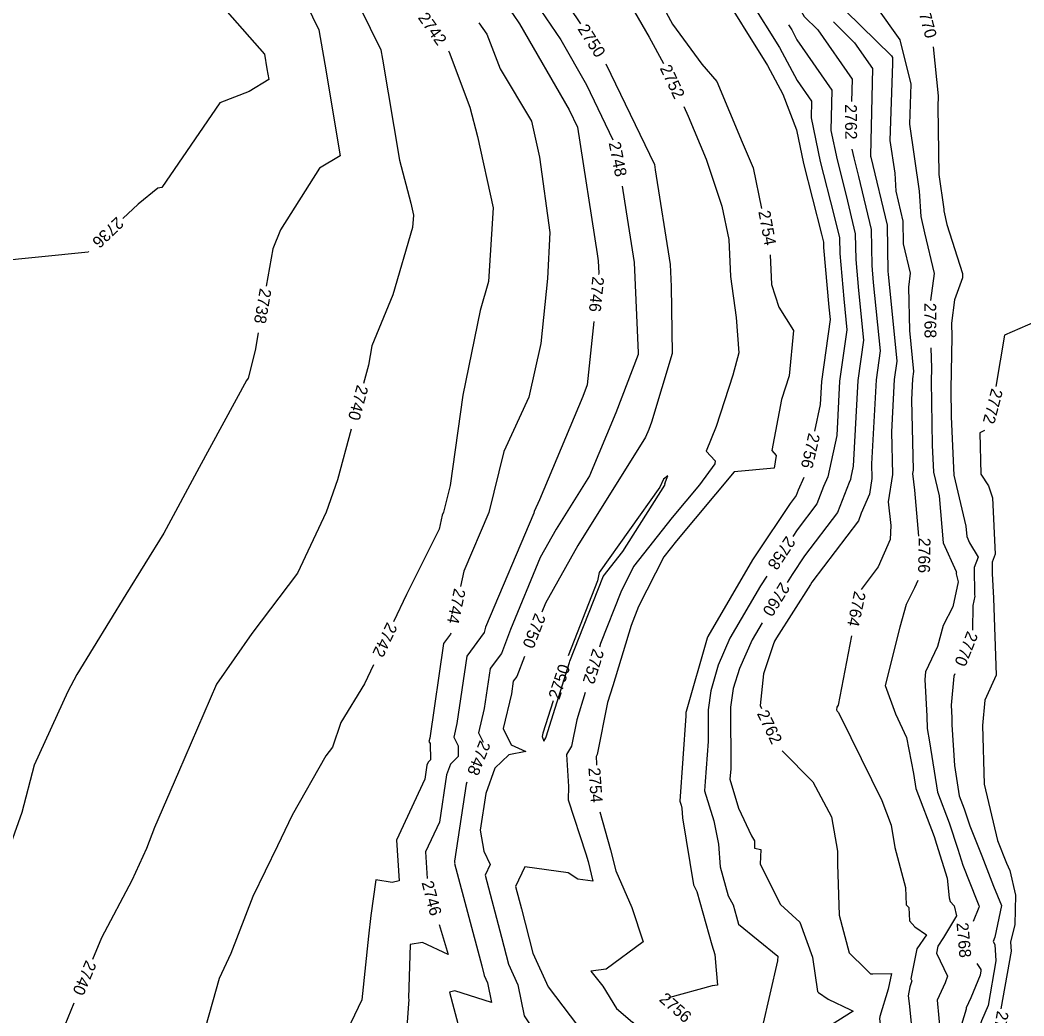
# Model space of a CAD drawing. Extents: x 1326424 to 1329294, y 1001359 to 1003823.
# Drawn here: x 1328101.5 to 1328270.7, y 1002132.9 to 1002300.7 of the extents above; entities that cross this region are included whole.
import ezdxf

# ---------------------------------------------------------------- set-up
doc = ezdxf.new("R2010")
doc.units = 0
doc.layers.add('Prop Rem of Exist Asph Pvmt', color=7, linetype='Continuous')
doc.layers.add('Scratch_Level_3', color=7, linetype='Continuous')

msp = doc.modelspace()

# ---------------------------------------------------------------- linework, layer by layer
at = {"layer": 'Prop Rem of Exist Asph Pvmt'}
for points in [[(1328137.93, 1002329.46), (1328145.65, 1002320.15), (1328150.16, 1002314.83), (1328157, 1002306.62), (1328162.33, 1002295.68), (1328162.6, 1002294.14), (1328165.48, 1002277.1), (1328167.37, 1002269.89), (1328167.81, 1002267.87), (1328167.68, 1002265.79), (1328164.34, 1002254.4), (1328160.8, 1002245.85), (1328160.23, 1002242.57), (1328159.4, 1002239.5)], [(1328231.01, 1002299.92), (1328231.55, 1002299.05), (1328232.44, 1002297.39), (1328238.31, 1002288.9), (1328238.16, 1002282.13), (1328239.19, 1002277.18), (1328240.74, 1002271.14), (1328242.27, 1002264.73), (1328242.34, 1002260.37), (1328242.8, 1002255.13), (1328243.64, 1002246.77), (1328242.69, 1002239.99), (1328241.92, 1002225.56), (1328241.53, 1002223.72), (1328241.44, 1002223.31), (1328241.21, 1002222.79), (1328239.29, 1002217.78), (1328233.73, 1002210.44), (1328231.64, 1002207.31), (1328230.79, 1002205.97)], [(1328157.31, 1002231.78), (1328155, 1002223.25), (1328153.09, 1002217.79), (1328148.26, 1002207.56), (1328140.6, 1002197.4), (1328134.65, 1002188.82), (1328128.24, 1002174.02), (1328124.2, 1002164.7), (1328122.82, 1002161.15), (1328120.34, 1002155.77), (1328115.25, 1002146.09), (1328113.72, 1002142.46)], [(1328226.58, 1002199.17), (1328224.91, 1002196.32), (1328222.77, 1002191.46), (1328221.68, 1002188.13), (1328221.25, 1002184.96), (1328221.27, 1002174.56), (1328221.13, 1002172.86), (1328222.57, 1002167.97), (1328224.77, 1002163.31), (1328225.27, 1002162.46), (1328225.27, 1002161.2), (1328226.33, 1002160.97), (1328226.23, 1002158.54), (1328229.69, 1002151.71), (1328232.93, 1002148.73), (1328235.05, 1002142.83), (1328235.9, 1002137.07), (1328236.05, 1002136.9), (1328237.72, 1002135.76), (1328241.47, 1002133.99), (1328241.88, 1002133.77), (1328236.13, 1002130.1)], [(1328110.61, 1002135.08), (1328109.05, 1002131.38), (1328107.66, 1002126.41), (1328107.1, 1002124.52), (1328107.44, 1002122.93), (1328106.9, 1002102.21), (1328106.04, 1002097.76), (1328108.22, 1002082.7), (1328108.65, 1002078.85), (1328112.24, 1002054.51), (1328112.26, 1002052.45), (1328109.23, 1002044.54), (1328107.76, 1002040.24), (1328107.08, 1002037.12)]]:
    msp.add_lwpolyline(points, dxfattribs=at)
at = {"layer": 'Scratch_Level_3'}
for points in [[(1328139.62, 1002379.77), (1328143.78, 1002373.87), (1328144.33, 1002372.95), (1328151.49, 1002363.95), (1328151.79, 1002363.59), (1328157.98, 1002355.78), (1328156.78, 1002354.76), (1328157.22, 1002349.14), (1328166.57, 1002337.91), (1328169.93, 1002333.87), (1328170.75, 1002332.84), (1328180.63, 1002321.17), (1328181.53, 1002319.97), (1328190.61, 1002308.04), (1328195.95, 1002300.06)], [(1328151, 1002373.46), (1328154.11, 1002369.54), (1328160.69, 1002361.71), (1328161.49, 1002360.69), (1328172.13, 1002345.68), (1328175.32, 1002341.89), (1328183.23, 1002335.42), (1328185.56, 1002332.78), (1328190.87, 1002323.83), (1328193.47, 1002319.61), (1328199.59, 1002311.45), (1328202.83, 1002306.05), (1328207.52, 1002297.83), (1328209.94, 1002293.39)], [(1328197.03, 1002371.73), (1328195.77, 1002368.79), (1328195.7, 1002367.71), (1328196.38, 1002356.22), (1328196.43, 1002355.7), (1328196.91, 1002354.72), (1328197.27, 1002354.62), (1328197.82, 1002353.9), (1328206.59, 1002343.94), (1328209.29, 1002339.14), (1328210.4, 1002337.87), (1328211.41, 1002336.49), (1328219.13, 1002327.92), (1328222.05, 1002323.48), (1328224.74, 1002319.48), (1328225.76, 1002317.21), (1328226.53, 1002313.85), (1328233.67, 1002301.33), (1328235.96, 1002299.09), (1328241.73, 1002290.74), (1328241.65, 1002286.97)], [(1328141.79, 1002360.3), (1328143.05, 1002358.79), (1328146.88, 1002354.08), (1328155.36, 1002345.27), (1328162.04, 1002337.24), (1328163.15, 1002335.9), (1328170.43, 1002326.75), (1328176.73, 1002319.31), (1328182.53, 1002311.54), (1328187.62, 1002304.86), (1328192.63, 1002297.37), (1328196.97, 1002289.83), (1328201.44, 1002280.55)], [(1328173.12, 1002352.12), (1328173.78, 1002351.18), (1328180.48, 1002343.21), (1328182.75, 1002341.36), (1328195.06, 1002327.36), (1328195.45, 1002326.7), (1328201.41, 1002317.01), (1328201.88, 1002316.39), (1328209.33, 1002303.97), (1328209.69, 1002303.34), (1328211.49, 1002300.03), (1328216.41, 1002293.29), (1328218.94, 1002290.35), (1328223.21, 1002280.13), (1328225.04, 1002275.8), (1328226.49, 1002268.97)], [(1328239.7, 1002348.68), (1328240.07, 1002347.46), (1328238.43, 1002336.43), (1328238.65, 1002335.24), (1328237.85, 1002333.55), (1328239.15, 1002331.7), (1328239.49, 1002330.84), (1328240.93, 1002322.22), (1328239.53, 1002315.41), (1328239.58, 1002315.31), (1328239.64, 1002315.03), (1328240.52, 1002311.64), (1328243.31, 1002305.33), (1328245.72, 1002303.07), (1328249.76, 1002297.39), (1328251.62, 1002289.93), (1328251.39, 1002283.2), (1328253.05, 1002271.87), (1328253.3, 1002267.63), (1328253.92, 1002264.86), (1328255.53, 1002258.02), (1328254.95, 1002253.5)], [(1328150.78, 1002342.45), (1328156.72, 1002336.28), (1328156.85, 1002336.12), (1328163.83, 1002328.57), (1328170.12, 1002320.65), (1328172.83, 1002317.45), (1328183.53, 1002303.11), (1328184.62, 1002301.67), (1328185.7, 1002300.06), (1328194.05, 1002285.57), (1328195.45, 1002282.67), (1328198.75, 1002261.36), (1328198.93, 1002260.18), (1328199.03, 1002258.05), (1328199.01, 1002257.88)], [(1328103.19, 1002340.21), (1328117.91, 1002327), (1328119.9, 1002324.79), (1328124.54, 1002320.74), (1328125.71, 1002319.32), (1328131.13, 1002313.12), (1328136.44, 1002302.08), (1328142.7, 1002294.95), (1328143.13, 1002292.48), (1328143.43, 1002290.69), (1328140.12, 1002288.67), (1328135.22, 1002286.79), (1328125.42, 1002272.5), (1328124.76, 1002272.39), (1328121.43, 1002269.71), (1328118.86, 1002267.26)], [(1328118.53, 1002339.13), (1328118.82, 1002338.87), (1328128.45, 1002328.13), (1328130.11, 1002326.69), (1328137.77, 1002317.39), (1328145.13, 1002308.96), (1328149.72, 1002303.46), (1328151.86, 1002299.06), (1328152.86, 1002293.31), (1328155.48, 1002277.87), (1328152.01, 1002275.75), (1328145.42, 1002265.35), (1328144.11, 1002262.19), (1328143.02, 1002255.89)], [(1328207.87, 1002323.83), (1328208.59, 1002322.78), (1328209.35, 1002321.94), (1328209.95, 1002321.02), (1328218.49, 1002307.61), (1328218.99, 1002306.69), (1328227.48, 1002293.09), (1328230.08, 1002288.24), (1328232.37, 1002282.25), (1328233.54, 1002276.58), (1328236.6, 1002264.63), (1328236.92, 1002263.31), (1328236.93, 1002262.41), (1328237.81, 1002252.37), (1328238.02, 1002250.27), (1328236.55, 1002239.8), (1328236.35, 1002235.94), (1328235.4, 1002231.45)], [(1328236.66, 1002308.58), (1328237.16, 1002306.37), (1328238.04, 1002304.83), (1328248.36, 1002294.71), (1328248.56, 1002294.43), (1328248.54, 1002293.4), (1328248.11, 1002280.43), (1328248.92, 1002274.9), (1328249.09, 1002271.88), (1328250.29, 1002266.86), (1328250.36, 1002263.01), (1328251.52, 1002258.09), (1328251.21, 1002255.7), (1328251.38, 1002248.39), (1328252.07, 1002241.51), (1328251.9, 1002240.28), (1328251.71, 1002236.72), (1328252.02, 1002224.88), (1328251.93, 1002224.33), (1328252.24, 1002221.53), (1328252.92, 1002213.75)], [(1328222.54, 1002307.72), (1328224.52, 1002304.07), (1328229.51, 1002296.07), (1328232.47, 1002290.56), (1328234.9, 1002287.05), (1328234.84, 1002284.26), (1328236.37, 1002276.88), (1328238.67, 1002267.88), (1328239.59, 1002264.02), (1328239.64, 1002261.39), (1328240.31, 1002253.75), (1328240.83, 1002248.52), (1328239.62, 1002239.9), (1328239.13, 1002230.75), (1328237.94, 1002225.04), (1328237.66, 1002223.77), (1328236.93, 1002222.15), (1328235.79, 1002219.19), (1328232.5, 1002214.85), (1328231.75, 1002213.72)], [(1328178.84, 1002300.26), (1328180.21, 1002298.33), (1328182.41, 1002292.5), (1328187.71, 1002283.66), (1328189.04, 1002277.6), (1328190.78, 1002264.9), (1328190.4, 1002257.17), (1328189.3, 1002246.23), (1328187.24, 1002237.19), (1328183.02, 1002228.03), (1328180.5, 1002217.74), (1328176.3, 1002207.87), (1328175.75, 1002205.27)], [(1328238.57, 1002300.41), (1328242.16, 1002296.9), (1328245.14, 1002292.58), (1328244.82, 1002277.88), (1328244.84, 1002277.77), (1328244.87, 1002277.64), (1328247.62, 1002266.15), (1328247.75, 1002258.34), (1328247.79, 1002257.89), (1328249.26, 1002243.26), (1328248.83, 1002240.18), (1328248.35, 1002231.32), (1328248.54, 1002224.17), (1328247.82, 1002219.55), (1328248.26, 1002215.56), (1328248.14, 1002213.2), (1328246.13, 1002208.58), (1328243.25, 1002204.77)], [(1328255.41, 1002296.18), (1328256.24, 1002287.94), (1328256.15, 1002286.12), (1328256.33, 1002274.72), (1328257.19, 1002268.85), (1328257.2, 1002268.56), (1328257.71, 1002266.27), (1328260.33, 1002258.04), (1328260.34, 1002257.3), (1328258.98, 1002253.58), (1328258.48, 1002249.68), (1328258.53, 1002247.35), (1328258.34, 1002238.56), (1328258.43, 1002233.9), (1328258.88, 1002224.03), (1328260.91, 1002215.44), (1328261.06, 1002213.72), (1328261.53, 1002212.67), (1328262.95, 1002210.25), (1328262.3, 1002208.5), (1328262.34, 1002203.88), (1328262.4, 1002203.66), (1328262.06, 1002202.09), (1328262.02, 1002197.93)], [(1328173.7, 1002295.51), (1328173.82, 1002295.33), (1328177.33, 1002286.03), (1328178.62, 1002281.1), (1328181.25, 1002269.09), (1328180.46, 1002256.68), (1328179.04, 1002251.81), (1328176.14, 1002237.51), (1328173.99, 1002222.31), (1328172.9, 1002217.83), (1328172.67, 1002217.3), (1328172.17, 1002214.94), (1328166.64, 1002203.94), (1328164.46, 1002199.34)], [(1328200.26, 1002293.33), (1328208.43, 1002276.36), (1328208.57, 1002275.5), (1328211.06, 1002259.53), (1328211.23, 1002255.82), (1328211.42, 1002244.52), (1328207.93, 1002232.97), (1328207.47, 1002231.75), (1328206.92, 1002230.44), (1328195.5, 1002212.2), (1328190.08, 1002202.49), (1328189.43, 1002200.94)], [(1328113.09, 1002261.72), (1328113, 1002261.62), (1328096.75, 1002259.97), (1328092.42, 1002254), (1328076, 1002240.07), (1328074.31, 1002239.33), (1328066.54, 1002261.1), (1328066.32, 1002263.41), (1328061.7, 1002267.92), (1328059.91, 1002268.1), (1328056.3, 1002278.19), (1328055.03, 1002286.46)], [(1328213.36, 1002286.17), (1328214.11, 1002284.52), (1328217.12, 1002277.31), (1328219.77, 1002269.36), (1328220.96, 1002263.77), (1328221.25, 1002257.49), (1328222.2, 1002250.63), (1328222.63, 1002244.65), (1328221.66, 1002240.89), (1328218.83, 1002232.24), (1328217.15, 1002228.1), (1328218.67, 1002226.47), (1328218.62, 1002225.93), (1328216.03, 1002222.44), (1328211.41, 1002216.93), (1328204.91, 1002208.64), (1328202.74, 1002204.36), (1328199.35, 1002195.71), (1328199.15, 1002195.05)], [(1328295.82, 1002286.46), (1328296.84, 1002277.77), (1328297.4, 1002273.85), (1328296.72, 1002269.77), (1328294.06, 1002258.46), (1328293.88, 1002258.42), (1328293.58, 1002258.4), (1328292.57, 1002253.12), (1328292.62, 1002243.11), (1328293.35, 1002243.13), (1328291.28, 1002238.95), (1328289.74, 1002234.66), (1328289.29, 1002236.02), (1328288.86, 1002236.25), (1328286.62, 1002241.56), (1328280.65, 1002253.93), (1328276.94, 1002254.24), (1328273.37, 1002250.34), (1328272.58, 1002249.87), (1328267.43, 1002247.63), (1328265.97, 1002238.99)], [(1328241.7, 1002278.99), (1328242.01, 1002277.48), (1328242.8, 1002274.39), (1328244.94, 1002265.44), (1328245.04, 1002259.35), (1328245.29, 1002256.51), (1328246.45, 1002245.01), (1328245.76, 1002240.09), (1328245, 1002225.93), (1328245.07, 1002223.47), (1328244.66, 1002220.86), (1328243.27, 1002217.64), (1328242.79, 1002216.37), (1328234.97, 1002206.03), (1328234.71, 1002205.65), (1328229.01, 1002196.64), (1328228.67, 1002196.06), (1328228.41, 1002195.46), (1328226.8, 1002190.58), (1328226.24, 1002185.25), (1328226.46, 1002184.76)], [(1328202.99, 1002272.74), (1328203.66, 1002268.43), (1328205, 1002259.86), (1328205.7, 1002244.65), (1328205.7, 1002244.53), (1328205.66, 1002244.4), (1328201.92, 1002234.52), (1328197.48, 1002223.94), (1328191.86, 1002214.96), (1328189.19, 1002210.19), (1328184.17, 1002198.06), (1328182.63, 1002194.03), (1328180.72, 1002191.45), (1328179.74, 1002184.71), (1328178.78, 1002180.64), (1328179.54, 1002179.08)], [(1328227.94, 1002261.15), (1328228.17, 1002256.15), (1328229.37, 1002252.33), (1328231.83, 1002248.41), (1328231.11, 1002240.78), (1328229.84, 1002236.8), (1328228.21, 1002228.22), (1328228.95, 1002227.37), (1328228.58, 1002225.24), (1328221.88, 1002224.62), (1328221.85, 1002224.58), (1328212.12, 1002212.96), (1328210.02, 1002210.29), (1328205.76, 1002201.92), (1328204.5, 1002198.71), (1328201.39, 1002188.57), (1328200.49, 1002185.72), (1328198.8, 1002176.99), (1328198.6, 1002176.67), (1328198.68, 1002175.42), (1328198.67, 1002175.21)], [(1328198.2, 1002249.92), (1328197.11, 1002239.26), (1328196.37, 1002237.3), (1328189.08, 1002219.91), (1328188.18, 1002217.95), (1328188.1, 1002217.65), (1328179.93, 1002198.43), (1328179.73, 1002197.52), (1328176.81, 1002193.57), (1328175.15, 1002182.23), (1328174.61, 1002179.91), (1328175.33, 1002178.42), (1328175.37, 1002176.64), (1328174.04, 1002175.36), (1328173.41, 1002173.59), (1328172.18, 1002165.6), (1328169.85, 1002160.6), (1328170.14, 1002156.08)], [(1328141.65, 1002248), (1328141.14, 1002245.07), (1328139.99, 1002240.41), (1328139.71, 1002239.98), (1328131.71, 1002225.32), (1328125.76, 1002214.25), (1328119.36, 1002203.97), (1328111.12, 1002190.45), (1328109.57, 1002187.58), (1328103.9, 1002175.21), (1328101.84, 1002167.22), (1328099.37, 1002160.26), (1328099.03, 1002158.3)], [(1328255.01, 1002245.5), (1328255.09, 1002242.07), (1328255.04, 1002239.9), (1328255.24, 1002229.12), (1328255.45, 1002224.54), (1328256.39, 1002220.55), (1328257.09, 1002212.65), (1328259.24, 1002207.79), (1328259.3, 1002207.69), (1328259.27, 1002207.62), (1328259.28, 1002207.44), (1328259.59, 1002206.07), (1328258.7, 1002201.86), (1328257.1, 1002198.7), (1328256.13, 1002195.19), (1328254.09, 1002190.93), (1328253.97, 1002189.6), (1328254.31, 1002183.45), (1328254.36, 1002181.36), (1328254.79, 1002179.11), (1328256.13, 1002170.64), (1328258.08, 1002165.5), (1328259.56, 1002161.03), (1328260.4, 1002158.33), (1328262.76, 1002152.4), (1328263.1, 1002151.53), (1328263.15, 1002151.42), (1328263.11, 1002151.22), (1328262.14, 1002148.84)], [(1328264.04, 1002231.55), (1328263.23, 1002231.16), (1328263.4, 1002224.2), (1328264.73, 1002222.27), (1328265.38, 1002220.23), (1328265.84, 1002210.75), (1328265.33, 1002209.39), (1328265.35, 1002207.5), (1328265.57, 1002203.32), (1328265.99, 1002190.34), (1328264.08, 1002186.16), (1328263.68, 1002181.85), (1328264, 1002172.01), (1328266.25, 1002162.52), (1328267.77, 1002158.7), (1328268.02, 1002158.06), (1328268.28, 1002157.42), (1328269.25, 1002153.3), (1328269.13, 1002148.37), (1328268.43, 1002145.35), (1328268.52, 1002143.88), (1328266.77, 1002134.13)], [(1328203.08, 1002211.17), (1328210.18, 1002222.34), (1328210.21, 1002222.65), (1328210.19, 1002222.67), (1328210.7, 1002223.93), (1328209.93, 1002223.36), (1328209.36, 1002222.01), (1328199.09, 1002207.63), (1328198.81, 1002206.23), (1328193.87, 1002193.61)], [(1328233.61, 1002223.66), (1328232.64, 1002221.52), (1328232.29, 1002220.6), (1328231.27, 1002219.25), (1328225.49, 1002210.64), (1328224.95, 1002209.78), (1328217.4, 1002196.85), (1328217.29, 1002196.61), (1328213.76, 1002184.22), (1328213.74, 1002184.08), (1328213.74, 1002183.83), (1328213.72, 1002183.52), (1328212.71, 1002169.13), (1328212.92, 1002168.46), (1328213.02, 1002167.93), (1328213.13, 1002166.34), (1328214.98, 1002155.05), (1328215.59, 1002153.93), (1328218.12, 1002144.92), (1328218.62, 1002143.31), (1328218.83, 1002140.63), (1328219.04, 1002138.12), (1328218.13, 1002138.04), (1328210.79, 1002135.98)], [(1328191.36, 1002186.02), (1328189.64, 1002180.58), (1328189.5, 1002180.01), (1328189.77, 1002179.21), (1328190.13, 1002179.78), (1328190.16, 1002179.97), (1328194.13, 1002192.48), (1328194.19, 1002192.7), (1328199.71, 1002206.81), (1328199.8, 1002206.99), (1328203.08, 1002211.17)], [(1328227.34, 1002207.05), (1328226.3, 1002205.4), (1328221.15, 1002196.59), (1328219.16, 1002192.06), (1328217.93, 1002187.72), (1328217.5, 1002184.52), (1328217.5, 1002179.2), (1328216.97, 1002172.46), (1328216.86, 1002170.88), (1328218.43, 1002165.84), (1328219.22, 1002161.88), (1328219.48, 1002158.07), (1328220.84, 1002153.17), (1328221.67, 1002151.64), (1328222.23, 1002149.65), (1328222.6, 1002148.43), (1328229.19, 1002143), (1328229.18, 1002142.2), (1328226.55, 1002131.01)], [(1328252.79, 1002206.3), (1328252.26, 1002205.06), (1328250.83, 1002202.23), (1328249.78, 1002198.44), (1328247.3, 1002188.59), (1328249.02, 1002183.82), (1328250.91, 1002179.87), (1328252.08, 1002173.77), (1328252.48, 1002171.26), (1328255.53, 1002163.19), (1328255.97, 1002161.86), (1328257.75, 1002156.15), (1328258.07, 1002152.82), (1328258.26, 1002152.25), (1328258.91, 1002151.48), (1328259.31, 1002149.79), (1328257.14, 1002146.13), (1328256.18, 1002144.72), (1328255.94, 1002143.52), (1328257.78, 1002139.65), (1328257.42, 1002138.54), (1328256.05, 1002135.58), (1328256.65, 1002129.54)], [(1328174.09, 1002197.45), (1328174.05, 1002197.26), (1328172.89, 1002195.7), (1328170.57, 1002179.75), (1328170.43, 1002179.18), (1328170.61, 1002178.82), (1328170.68, 1002176.08), (1328170.29, 1002175.71), (1328170.1, 1002175.19), (1328169.74, 1002172.85), (1328164.96, 1002162.58), (1328165.4, 1002155.7), (1328164.24, 1002155.43), (1328161.5, 1002155.85), (1328160.64, 1002149.86), (1328160.24, 1002146.37), (1328159.14, 1002135.67), (1328154.16, 1002125.34), (1328151.31, 1002117.38), (1328150.69, 1002105.26)], [(1328241.6, 1002196.99), (1328239.37, 1002185.29), (1328239.15, 1002184.94), (1328239.11, 1002184.54), (1328239.21, 1002184.3), (1328239.39, 1002184.12), (1328239.79, 1002183.37), (1328246.75, 1002169.25), (1328248.31, 1002165.11), (1328248.94, 1002161.34), (1328250.75, 1002154.6), (1328250.84, 1002151.65), (1328251.27, 1002151.23), (1328251.38, 1002148.99), (1328252.29, 1002147.93), (1328254.26, 1002146.6), (1328252.66, 1002144.25), (1328251.63, 1002139.17), (1328251.77, 1002138.88), (1328251.45, 1002137.86), (1328251.17, 1002136.35), (1328251.35, 1002135.04), (1328252.35, 1002125.02)], [(1328186.52, 1002193.49), (1328185.24, 1002190.14), (1328184.63, 1002189.33), (1328184.32, 1002187.2), (1328182.95, 1002181.36), (1328184.28, 1002178.62), (1328186.74, 1002177.48), (1328183.91, 1002176.94), (1328181.55, 1002174.66), (1328180.02, 1002170.39), (1328179.07, 1002164.22), (1328179.67, 1002160.72), (1328180.72, 1002158.47), (1328179.89, 1002156.68), (1328182.68, 1002146.2), (1328183.84, 1002141.66), (1328185.42, 1002138.19), (1328186.47, 1002132.95), (1328189.85, 1002127.87), (1328185.66, 1002127), (1328183.85, 1002126.65), (1328184.16, 1002125.5), (1328183.96, 1002122.96), (1328181.89, 1002107.19)], [(1328161.06, 1002192.1), (1328159.57, 1002188.92), (1328155.58, 1002182.38), (1328154.2, 1002178.24), (1328153.03, 1002176.74), (1328147.39, 1002166.79), (1328144.91, 1002161.62), (1328140.75, 1002153.04), (1328137.03, 1002143.45), (1328135.1, 1002139.25), (1328132.19, 1002129.06), (1328128.05, 1002115.64), (1328128.5, 1002107.62), (1328128.99, 1002099.36)], [(1328259.04, 1002190.58), (1328258.85, 1002190.19), (1328258.41, 1002185.32), (1328258.53, 1002183.16), (1328258.56, 1002181.96), (1328258.98, 1002175.15), (1328259.79, 1002170.02), (1328260.62, 1002167.82), (1328261.57, 1002164.95), (1328263.57, 1002159.93), (1328265.56, 1002154.79), (1328266.9, 1002151.53), (1328265.77, 1002146.24), (1328265.47, 1002145.5), (1328265.8, 1002144.97), (1328265.97, 1002142.2), (1328264.63, 1002134.73), (1328263.54, 1002132.12), (1328261.58, 1002126.07), (1328258.97, 1002117.54), (1328257.31, 1002112.07), (1328256.4, 1002108.84), (1328255.87, 1002107.16), (1328252.02, 1002094.39)], [(1328196.77, 1002187.41), (1328195.33, 1002182.84), (1328194.46, 1002178.39), (1328193.58, 1002177), (1328193.93, 1002171.57), (1328193.86, 1002169.37), (1328196.89, 1002160.23), (1328197.24, 1002158.97), (1328198.05, 1002155.66), (1328195.51, 1002156.01), (1328193.86, 1002157.08), (1328186.57, 1002158.04), (1328185.03, 1002154.73), (1328186.03, 1002150.99), (1328187.92, 1002143.54), (1328190.51, 1002137.87), (1328190.52, 1002137.87), (1328190.52, 1002137.86), (1328196.71, 1002129.69)], [(1328229.92, 1002177.59), (1328235.12, 1002172.38), (1328238.26, 1002166.48), (1328239.25, 1002160.72), (1328239.29, 1002158.49), (1328239.55, 1002149.92), (1328241.22, 1002143.6), (1328244.07, 1002140.8), (1328244.85, 1002140.01), (1328245.22, 1002140.03), (1328248.36, 1002140.12), (1328247.82, 1002137.48), (1328246.4, 1002132.83), (1328246.33, 1002132.48), (1328246.92, 1002128.11), (1328245.58, 1002123.88), (1328243.96, 1002123.75), (1328245.51, 1002112.86), (1328243.97, 1002107.99), (1328242.8, 1002104.1), (1328240.41, 1002098.18), (1328236.95, 1002091.26), (1328236.72, 1002089.81)], [(1328176.84, 1002172.32), (1328176.72, 1002171.99), (1328174.72, 1002159), (1328174.75, 1002158.83), (1328174.8, 1002158.72), (1328174.76, 1002158.63), (1328179.34, 1002141.41), (1328179.76, 1002139.78), (1328180.32, 1002138.53), (1328180.99, 1002135.23), (1328174.81, 1002137.15), (1328173.88, 1002136.97), (1328175.6, 1002130.61), (1328174.48, 1002116.58), (1328173.6, 1002109.83), (1328174.39, 1002093.12), (1328174.85, 1002087), (1328174.78, 1002083.72), (1328174.81, 1002082.89)], [(1328199.24, 1002167.33), (1328201.03, 1002160.94), (1328201.9, 1002157.4), (1328204.62, 1002151.23), (1328206.55, 1002145.44), (1328200.31, 1002140.84), (1328197.72, 1002140.5), (1328199.08, 1002138.79), (1328199.71, 1002137.96), (1328202.05, 1002134.19), (1328204.74, 1002131.89), (1328207.39, 1002128.8), (1328213.43, 1002126.04), (1328216.79, 1002123.71), (1328218.2, 1002123.13), (1328224.85, 1002120.01), (1328225.11, 1002119.75), (1328225.86, 1002119.82), (1328227.06, 1002118.23), (1328226.71, 1002114.53), (1328226.32, 1002100.93), (1328225.13, 1002098.55), (1328223.76, 1002090.12)], [(1328172.17, 1002148.36), (1328173.66, 1002143.28), (1328169.36, 1002145.31), (1328167.26, 1002144.98), (1328166.99, 1002135.91), (1328167.04, 1002135.73), (1328166.98, 1002134.99), (1328165.64, 1002116.2), (1328166.86, 1002101), (1328167.33, 1002091.06), (1328167.52, 1002088.5), (1328168.68, 1002075.86), (1328168.95, 1002068.36), (1328169.31, 1002063.37), (1328169.85, 1002057.38)], [(1328262.77, 1002141.77), (1328263.4, 1002140.78), (1328263.42, 1002140.52), (1328263.29, 1002139.81), (1328261.71, 1002136), (1328260.93, 1002134.31), (1328260.95, 1002134.06), (1328255.76, 1002117.08)]]:
    msp.add_lwpolyline(points, dxfattribs=at)

# ---------------------------------------------------------------- texts
at = {"layer": 'Prop Rem of Exist Asph Pvmt'}
for s, rotation, p in [('2740', 254.8705, (1328158.32, 1002239.36)), ('2760', 238.235, (1328229.68, 1002206.15)), ('2740', 247.1576, (1328112.64, 1002142.46))]:
    msp.add_text(s, height=2, rotation=rotation, dxfattribs=at).set_placement(p)
at = {"layer": 'Scratch_Level_3'}
for s, rotation, p in [('2770', 284.8682, (1328252.59, 1002303.24)), ('2742', 305.3597, (1328168.49, 1002301.11)), ('2750', 302.6278, (1328195.41, 1002299.22)), ('2752', 295.3599, (1328209.28, 1002292.62)), ('2762', 270.3966, (1328240.53, 1002286.53)), ('2748', 281.2085, (1328200.7, 1002280.02)), ('2736', 223.9122, (1328117.82, 1002267.69)), ('2754', 280.4674, (1328225.92, 1002268.46)), ('2746', 264.1671, (1328197.98, 1002257.57)), ('2738', 260.1406, (1328141.95, 1002255.62)), ('2768', 270.441, (1328253.89, 1002253.06)), ('2772', 255.4475, (1328265.23, 1002238.77)), ('2756', 257.0461, (1328234.41, 1002231.25)), ('2758', 236.5789, (1328230.66, 1002213.94)), ('2766', 268.9965, (1328252.95, 1002213.52)), ('2744', 258.0395, (1328174.68, 1002205.07)), ('2764', 258.0052, (1328242.11, 1002204.61)), ('2750', 248.6063, (1328188.32, 1002200.93)), ('2742', 244.8462, (1328163.38, 1002199.39)), ('2770', 247.8945, (1328261.17, 1002197.9)), ('2752', 252.7403, (1328198.08, 1002194.94)), ('2750', 71.7017, (1328192.39, 1002186.12)), ('2762', 295.7284, (1328225.65, 1002183.89)), ('2748', 248.2268, (1328179.03, 1002179.5)), ('2754', 274.1256, (1328197.29, 1002174.72)), ('2746', 284.7325, (1328169.17, 1002155.41)), ('2768', 275.1317, (1328259.31, 1002148.6)), ('2756', 318.8406, (1328209.08, 1002135.56)), ('2772', 260.3496, (1328266.16, 1002133.89))]:
    msp.add_text(s, height=2, rotation=rotation, dxfattribs=at).set_placement(p)

doc.saveas('drawing.dxf')
